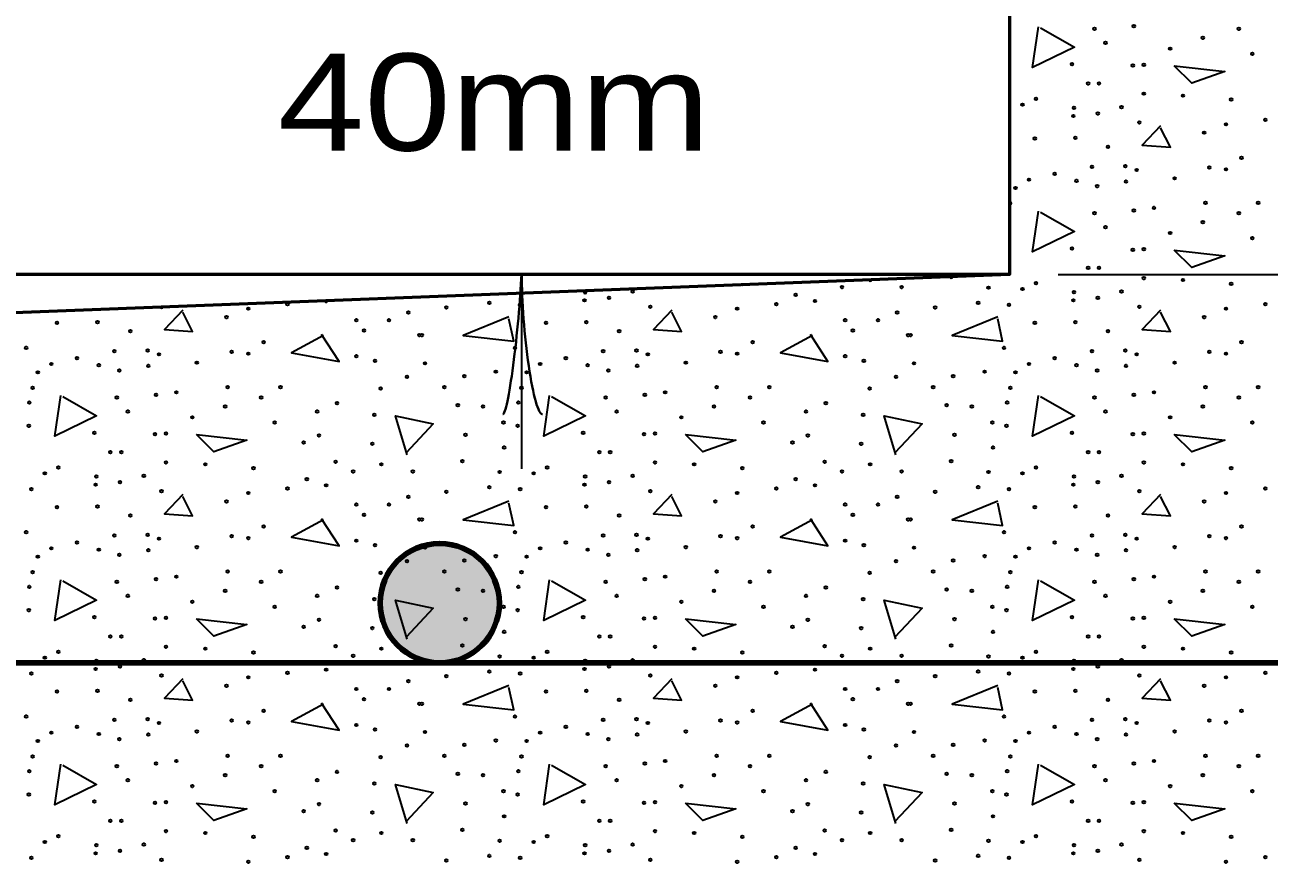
# Model space of a CAD drawing. Extents: x 442 to 1297, y -1132 to -588.
# Drawn here: x 631.58 to 662.37, y -976.12 to -955.39 of the extents above; entities that cross this region are included whole.
import ezdxf
from ezdxf.enums import TextEntityAlignment as Align

# ---------------------------------------------------------------- set-up
doc = ezdxf.new("R2010")
doc.units = 0
doc.header["$LTSCALE"] = 0.96
doc.layers.add('1', color=7, linetype='Continuous', lineweight=35)

msp = doc.modelspace()

# ---------------------------------------------------------------- hatches: boundary and pattern name
at = {"layer": '1'}
msp.add_hatch(color=256, dxfattribs=at).paths.add_polyline_path([(643.3225, -969.6926, 1), (640.3727, -969.6926, 1)])

# ---------------------------------------------------------------- linework, layer by layer
at = {"layer": '1', "lineweight": 53}
msp.add_line((655.9476, -961.5675), (589.3476, -961.5675), dxfattribs=at)
at = {"layer": '1'}
for p, q in [((643.8721, -961.5675), (643.8721, -966.3675)), ((657.1476, -961.5675), (691.5175, -961.5675))]:
    msp.add_line(p, q, dxfattribs=at)
at = {"layer": '1', "lineweight": 106}
msp.add_line((579.7476, -971.1675), (665.8476, -971.1675), dxfattribs=at)
at = {"layer": '1', "lineweight": 53}
msp.add_lwpolyline([(668.5476, -884.2076), (668.5476, -888.4076), (660.1476, -888.4076), (660.1476, -902.8076), (655.9476, -902.8076), (655.9476, -961.5675), (624.6664, -962.7675), (624.6664, -981.1136)], dxfattribs=at)
at = {"layer": '1'}
for points in [[(656.7098, -955.4627), (657.5498, -955.9427), (656.5178, -956.4467), (656.6618, -955.4387)], [(659.6858, -957.8867), (659.2298, -958.3667), (659.9258, -958.4147), (659.6858, -957.9347)], [(656.7098, -960.0227), (657.5498, -960.5027), (656.5178, -961.0067), (656.6618, -959.9987)], [(635.4938, -962.4467), (635.0378, -962.9267), (635.7338, -962.9747), (635.4938, -962.4947)], [(643.5578, -962.6147), (642.4298, -963.0707), (643.6778, -963.2147), (643.5578, -962.6627)], [(647.5898, -962.4467), (647.1338, -962.9267), (647.8298, -962.9747), (647.5898, -962.4947)], [(655.6538, -962.6147), (654.5258, -963.0707), (655.7738, -963.2147), (655.6538, -962.6627)], [(659.6858, -962.4467), (659.2298, -962.9267), (659.9258, -962.9747), (659.6858, -962.4947)], [(638.9738, -963.0707), (638.1818, -963.5027), (639.3578, -963.7187), (638.9258, -963.0467)], [(651.0698, -963.0707), (650.2778, -963.5027), (651.4538, -963.7187), (651.0218, -963.0467)], [(632.5178, -964.5827), (633.3578, -965.0627), (632.3258, -965.5667), (632.4698, -964.5587)], [(644.6138, -964.5827), (645.4538, -965.0627), (644.4218, -965.5667), (644.5658, -964.5587)], [(656.7098, -964.5827), (657.5498, -965.0627), (656.5178, -965.5667), (656.6618, -964.5587)], [(641.0378, -966.0227), (640.7498, -965.0627), (641.6858, -965.2547), (641.0138, -965.9747)], [(653.1338, -966.0227), (652.8458, -965.0627), (653.7818, -965.2547), (653.1098, -965.9747)], [(635.4938, -967.0067), (635.0378, -967.4867), (635.7338, -967.5347), (635.4938, -967.0547)], [(643.5578, -967.1747), (642.4298, -967.6307), (643.6778, -967.7747), (643.5578, -967.2227)], [(647.5898, -967.0067), (647.1338, -967.4867), (647.8298, -967.5347), (647.5898, -967.0547)], [(655.6538, -967.1747), (654.5258, -967.6307), (655.7738, -967.7747), (655.6538, -967.2227)], [(659.6858, -967.0067), (659.2298, -967.4867), (659.9258, -967.5347), (659.6858, -967.0547)], [(638.9738, -967.6307), (638.1818, -968.0627), (639.3578, -968.2787), (638.9258, -967.6067)], [(651.0698, -967.6307), (650.2778, -968.0627), (651.4538, -968.2787), (651.0218, -967.6067)], [(632.5178, -969.1427), (633.3578, -969.6227), (632.3258, -970.1267), (632.4698, -969.1187)], [(644.6138, -969.1427), (645.4538, -969.6227), (644.4218, -970.1267), (644.5658, -969.1187)], [(656.7098, -969.1427), (657.5498, -969.6227), (656.5178, -970.1267), (656.6618, -969.1187)], [(641.0378, -970.5827), (640.7498, -969.6227), (641.6858, -969.8147), (641.0138, -970.5347)], [(653.1338, -970.5827), (652.8458, -969.6227), (653.7818, -969.8147), (653.1098, -970.5347)], [(635.4938, -971.5667), (635.0378, -972.0467), (635.7338, -972.0947), (635.4938, -971.6147)], [(647.5898, -971.5667), (647.1338, -972.0467), (647.8298, -972.0947), (647.5898, -971.6147)], [(659.6858, -971.5667), (659.2298, -972.0467), (659.9258, -972.0947), (659.6858, -971.6147)], [(643.5578, -971.7347), (642.4298, -972.1907), (643.6778, -972.3347), (643.5578, -971.7827)], [(655.6538, -971.7347), (654.5258, -972.1907), (655.7738, -972.3347), (655.6538, -971.7827)], [(638.9738, -972.1907), (638.1818, -972.6227), (639.3578, -972.8387), (638.9258, -972.1667)], [(651.0698, -972.1907), (650.2778, -972.6227), (651.4538, -972.8387), (651.0218, -972.1667)], [(632.5178, -973.7027), (633.3578, -974.1827), (632.3258, -974.6867), (632.4698, -973.6787)], [(644.6138, -973.7027), (645.4538, -974.1827), (644.4218, -974.6867), (644.5658, -973.6787)], [(656.7098, -973.7027), (657.5498, -974.1827), (656.5178, -974.6867), (656.6618, -973.6787)], [(641.0378, -975.1427), (640.7498, -974.1827), (641.6858, -974.3747), (641.0138, -975.0947)], [(653.1338, -975.1427), (652.8458, -974.1827), (653.7818, -974.3747), (653.1098, -975.0947)]]:
    msp.add_lwpolyline(points, dxfattribs=at)
for points in [[(660.0218, -956.3987), (661.2698, -956.5427), (660.4538, -956.8307)], [(660.0218, -960.9587), (661.2698, -961.1027), (660.4538, -961.3907)], [(635.8298, -965.5187), (637.0778, -965.6627), (636.2618, -965.9507)], [(647.9258, -965.5187), (649.1738, -965.6627), (648.3578, -965.9507)], [(660.0218, -965.5187), (661.2698, -965.6627), (660.4538, -965.9507)], [(635.8298, -970.0787), (637.0778, -970.2227), (636.2618, -970.5107)], [(647.9258, -970.0787), (649.1738, -970.2227), (648.3578, -970.5107)], [(660.0218, -970.0787), (661.2698, -970.2227), (660.4538, -970.5107)], [(635.8298, -974.6387), (637.0778, -974.7827), (636.2618, -975.0707)], [(647.9258, -974.6387), (649.1738, -974.7827), (648.3578, -975.0707)], [(660.0218, -974.6387), (661.2698, -974.7827), (660.4538, -975.0707)]]:
    msp.add_lwpolyline(points, close=True, dxfattribs=at)
for centre in [(658.0499, -955.4852), (659.0201, -955.4216), (661.6216, -955.4852), (658.3204, -955.8353), (660.731, -955.708), (659.9199, -955.9785), (661.9555, -956.1058), (657.4933, -956.3603), (658.9965, -956.3948), (659.2678, -956.3761), (657.891, -956.8376), (658.1613, -956.8376), (659.2678, -957.0921), (660.238, -957.1398), (656.2688, -957.3625), (656.6028, -957.2194), (657.5411, -957.4421), (658.7179, -957.4261), (661.4308, -957.2352), (657.5252, -957.6431), (658.1295, -957.5795), (662.2737, -957.7385), (659.1565, -957.8021), (660.7628, -958.0567), (661.3036, -957.8499), (656.5709, -958.1999), (657.5729, -958.184), (658.384, -958.4066), (661.6852, -958.6771), (657.9863, -958.8998), (658.8134, -958.8839), (659.0929, -958.9794), (660.89, -958.9158), (661.3036, -958.9635), (656.4278, -959.2181), (657.0639, -959.0748), (657.6047, -959.2498), (658.8292, -959.2657), (660.0312, -959.1862), (656.0938, -959.4248), (658.1137, -959.3771), (659.5222, -959.918), (660.7945, -959.7907), (662.0987, -959.7907), (658.0499, -960.0452), (659.0201, -959.9816), (661.6216, -960.0452), (658.3204, -960.3953), (659.9199, -960.5385), (660.731, -960.268), (661.9555, -960.6658), (657.4933, -960.9203), (658.9965, -960.9548), (659.2678, -960.9361), (657.891, -961.3976), (658.1613, -961.3976), (656.6028, -961.7794), (659.2678, -961.6521), (660.238, -961.6998), (661.4308, -961.7952), (646.6219, -961.9861), (650.6548, -962.0657), (651.7998, -961.8749), (653.2789, -961.8749), (655.4259, -961.8907), (656.2688, -961.9225), (657.5411, -962.0021), (658.7179, -961.9861), (637.1116, -962.4099), (638.0817, -962.2985), (642.0098, -962.3781), (643.0754, -962.2667), (643.8388, -962.3145), (645.4292, -962.2031), (646.0335, -962.1395), (647.0605, -962.3621), (649.2076, -962.4099), (650.1777, -962.2985), (651.1318, -962.219), (654.1058, -962.3781), (655.1714, -962.2667), (655.9348, -962.3145), (657.5252, -962.2031), (658.1295, -962.1395), (659.1565, -962.3621), (661.3036, -962.4099), (662.2737, -962.2985), (636.5708, -962.6167), (639.7833, -962.6962), (640.5944, -962.6962), (641.0716, -962.5053), (648.6668, -962.6167), (651.8793, -962.6962), (652.6904, -962.6962), (653.1676, -962.5053), (660.7628, -962.6167), (632.3789, -962.7599), (633.3809, -962.744), (634.192, -962.9666), (639.9742, -962.9508), (644.4749, -962.7599), (645.4769, -962.744), (646.288, -962.9666), (652.0702, -962.9508), (656.5709, -962.7599), (657.5729, -962.744), (658.384, -962.9666), (637.4932, -963.2371), (641.3419, -963.0621), (641.4055, -963.0621), (649.5892, -963.2371), (653.4379, -963.0621), (653.5015, -963.0621), (661.6852, -963.2371), (631.6155, -963.3803), (632.8719, -963.6348), (633.7943, -963.4598), (634.6214, -963.4439), (634.9009, -963.5394), (636.698, -963.4758), (637.1116, -963.5235), (639.7834, -963.5872), (643.7115, -963.3803), (644.9679, -963.6348), (645.8903, -963.4598), (646.7174, -963.4439), (646.9969, -963.5394), (648.794, -963.4758), (649.2076, -963.5235), (651.8794, -963.5872), (655.8075, -963.3803), (657.0639, -963.6348), (657.9863, -963.4598), (658.8134, -963.4439), (659.0929, -963.5394), (660.89, -963.4758), (661.3036, -963.5235), (632.2358, -963.7781), (633.4127, -963.8098), (633.9217, -963.9371), (634.6372, -963.8257), (635.8392, -963.7462), (640.2445, -963.6984), (641.4851, -963.7621), (644.3318, -963.7781), (645.5087, -963.8098), (646.0177, -963.9371), (646.7332, -963.8257), (647.9352, -963.7462), (652.3405, -963.6984), (653.5811, -963.7621), (656.4278, -963.7781), (657.6047, -963.8098), (658.1137, -963.9371), (658.8292, -963.8257), (660.0312, -963.7462), (631.9018, -963.9848), (641.0397, -964.0962), (642.4552, -964.0803), (643.2345, -963.9689), (643.9978, -963.9848), (653.1357, -964.0962), (654.5512, -964.0803), (655.3305, -963.9689), (656.0938, -963.9848), (631.7746, -964.3666), (634.8281, -964.5416), (635.3302, -964.478), (636.6025, -964.3507), (637.9067, -964.3507), (640.3877, -964.3826), (641.9622, -964.3507), (643.8706, -964.3666), (646.9241, -964.5416), (647.4262, -964.478), (648.6985, -964.3507), (650.0027, -964.3507), (652.4837, -964.3826), (654.0582, -964.3507), (655.9666, -964.3666), (659.0201, -964.5416), (659.5222, -964.478), (660.7945, -964.3507), (662.0987, -964.3507), (631.6951, -964.7325), (633.8579, -964.6052), (636.539, -964.828), (637.4296, -964.6052), (639.3062, -964.7485), (642.2961, -964.7962), (642.9163, -964.828), (643.7911, -964.7325), (645.9539, -964.6052), (648.635, -964.828), (649.5256, -964.6052), (651.4022, -964.7485), (654.3921, -964.7962), (655.0123, -964.828), (655.8871, -964.7325), (658.0499, -964.6052), (660.731, -964.828), (661.6216, -964.6052), (634.1284, -964.9553), (635.7279, -965.0985), (638.8132, -964.9553), (640.2286, -965.0348), (646.2244, -964.9553), (647.8239, -965.0985), (650.9092, -964.9553), (652.3246, -965.0348), (658.3204, -964.9553), (659.9199, -965.0985), (631.6792, -965.3053), (633.3013, -965.4803), (637.7635, -965.2258), (643.4253, -965.2258), (643.7752, -965.3053), (645.3973, -965.4803), (649.8595, -965.2258), (655.5213, -965.2258), (655.8712, -965.3053), (657.4933, -965.4803), (661.9555, -965.2258), (634.8045, -965.5148), (635.0758, -965.4961), (638.4792, -965.7189), (638.861, -965.5439), (640.1809, -965.7507), (642.4869, -965.528), (646.9005, -965.5148), (647.1718, -965.4961), (650.5752, -965.7189), (650.957, -965.5439), (652.2769, -965.7507), (654.5829, -965.528), (658.9965, -965.5148), (659.2678, -965.4961), (633.699, -965.9576), (633.9693, -965.9576), (643.4412, -965.8462), (645.795, -965.9576), (646.0653, -965.9576), (655.5372, -965.8462), (657.891, -965.9576), (658.1613, -965.9576), (632.4108, -966.3394), (635.0758, -966.2121), (636.046, -966.2598), (637.2388, -966.3552), (639.2744, -966.1962), (640.4036, -966.2598), (642.4075, -966.1802), (644.5068, -966.3394), (647.1718, -966.2121), (648.142, -966.2598), (649.3348, -966.3552), (651.3704, -966.1962), (652.4996, -966.2598), (654.5035, -966.1802), (656.6028, -966.3394), (659.2678, -966.2121), (660.238, -966.2598), (661.4308, -966.3552), (632.0768, -966.4825), (633.3491, -966.5621), (633.9375, -966.6995), (634.5259, -966.5461), (638.5588, -966.6257), (639.7038, -966.4349), (641.1829, -966.4349), (643.3299, -966.4507), (644.1728, -966.4825), (645.4451, -966.5621), (646.0335, -966.6995), (646.6219, -966.5461), (650.6548, -966.6257), (651.7998, -966.4349), (653.2789, -966.4349), (655.4259, -966.4507), (656.2688, -966.4825), (657.5411, -966.5621), (658.1295, -966.6995), (658.7179, -966.5461), (631.7428, -966.8745), (633.3332, -966.7631), (634.9645, -966.9221), (637.1116, -966.9699), (638.0817, -966.8585), (639.0358, -966.779), (642.0098, -966.9381), (643.0754, -966.8267), (643.8388, -966.8745), (645.4292, -966.7631), (647.0605, -966.9221), (649.2076, -966.9699), (650.1777, -966.8585), (651.1318, -966.779), (654.1058, -966.9381), (655.1714, -966.8267), (655.9348, -966.8745), (657.5252, -966.7631), (659.1565, -966.9221), (661.3036, -966.9699), (662.2737, -966.8585), (632.3789, -967.3199), (633.3809, -967.304), (636.5708, -967.1767), (639.7833, -967.2562), (640.5944, -967.2562), (641.0716, -967.0653), (644.4749, -967.3199), (645.4769, -967.304), (648.6668, -967.1767), (651.8793, -967.2562), (652.6904, -967.2562), (653.1676, -967.0653), (656.5709, -967.3199), (657.5729, -967.304), (660.7628, -967.1767), (634.192, -967.5266), (639.9742, -967.5108), (641.3419, -967.6221), (641.4055, -967.6221), (646.288, -967.5266), (652.0702, -967.5108), (653.4379, -967.6221), (653.5015, -967.6221), (658.384, -967.5266), (631.6155, -967.9403), (637.4932, -967.7971), (643.7115, -967.9403), (649.5892, -967.7971), (655.8075, -967.9403), (661.6852, -967.7971), (632.8719, -968.1948), (633.7943, -968.0198), (634.6214, -968.0039), (634.9009, -968.0994), (636.698, -968.0358), (637.1116, -968.0835), (639.7834, -968.1472), (640.2445, -968.2584), (644.9679, -968.1948), (645.8903, -968.0198), (646.7174, -968.0039), (646.9969, -968.0994), (648.794, -968.0358), (649.2076, -968.0835), (651.8794, -968.1472), (652.3405, -968.2584), (657.0639, -968.1948), (657.9863, -968.0198), (658.8134, -968.0039), (659.0929, -968.0994), (660.89, -968.0358), (661.3036, -968.0835), (631.9018, -968.5448), (632.2358, -968.3381), (633.4127, -968.3698), (633.9217, -968.4971), (634.6372, -968.3857), (635.8392, -968.3062), (641.4851, -968.3221), (643.2345, -968.5289), (643.9978, -968.5448), (644.3318, -968.3381), (645.5087, -968.3698), (646.0177, -968.4971), (646.7332, -968.3857), (647.9352, -968.3062), (653.5811, -968.3221), (655.3305, -968.5289), (656.0938, -968.5448), (656.4278, -968.3381), (657.6047, -968.3698), (658.1137, -968.4971), (658.8292, -968.3857), (660.0312, -968.3062), (641.0397, -968.6562), (642.4552, -968.6403), (653.1357, -968.6562), (654.5512, -968.6403), (631.7746, -968.9266), (633.8579, -969.1652), (634.8281, -969.1016), (635.3302, -969.038), (636.6025, -968.9107), (637.4296, -969.1652), (637.9067, -968.9107), (640.3877, -968.9426), (641.9622, -968.9107), (643.8706, -968.9266), (645.9539, -969.1652), (646.9241, -969.1016), (647.4262, -969.038), (648.6985, -968.9107), (649.5256, -969.1652), (650.0027, -968.9107), (652.4837, -968.9426), (654.0582, -968.9107), (655.9666, -968.9266), (658.0499, -969.1652), (659.0201, -969.1016), (659.5222, -969.038), (660.7945, -968.9107), (661.6216, -969.1652), (662.0987, -968.9107), (631.6951, -969.2925), (636.539, -969.388), (639.3062, -969.3085), (642.2961, -969.3562), (642.9163, -969.388), (643.7911, -969.2925), (648.635, -969.388), (651.4022, -969.3085), (654.3921, -969.3562), (655.0123, -969.388), (655.8871, -969.2925), (660.731, -969.388), (634.1284, -969.5153), (635.7279, -969.6585), (637.7635, -969.7858), (638.8132, -969.5153), (640.2286, -969.5948), (643.4253, -969.7858), (646.2244, -969.5153), (647.8239, -969.6585), (649.8595, -969.7858), (650.9092, -969.5153), (652.3246, -969.5948), (655.5213, -969.7858), (658.3204, -969.5153), (659.9199, -969.6585), (661.9555, -969.7858), (631.6792, -969.8653), (633.3013, -970.0403), (634.8045, -970.0748), (635.0758, -970.0561), (638.861, -970.1039), (642.4869, -970.088), (643.7752, -969.8653), (645.3973, -970.0403), (646.9005, -970.0748), (647.1718, -970.0561), (650.957, -970.1039), (654.5829, -970.088), (655.8712, -969.8653), (657.4933, -970.0403), (658.9965, -970.0748), (659.2678, -970.0561), (638.4792, -970.2789), (640.1809, -970.3107), (643.4412, -970.4062), (650.5752, -970.2789), (652.2769, -970.3107), (655.5372, -970.4062), (633.699, -970.5176), (633.9693, -970.5176), (645.795, -970.5176), (646.0653, -970.5176), (657.891, -970.5176), (658.1613, -970.5176), (632.4108, -970.8994), (635.0758, -970.7721), (636.046, -970.8198), (637.2388, -970.9152), (639.2744, -970.7562), (639.7038, -970.9949), (640.4036, -970.8198), (641.1829, -970.9949), (642.4075, -970.7402), (643.3299, -971.0107), (644.5068, -970.8994), (647.1718, -970.7721), (648.142, -970.8198), (649.3348, -970.9152), (651.3704, -970.7562), (651.7998, -970.9949), (652.4996, -970.8198), (653.2789, -970.9949), (654.5035, -970.7402), (655.4259, -971.0107), (656.6028, -970.8994), (659.2678, -970.7721), (660.238, -970.8198), (661.4308, -970.9152), (632.0768, -971.0425), (633.3332, -971.3231), (633.3491, -971.1221), (633.9375, -971.2595), (634.5259, -971.1061), (638.5588, -971.1857), (639.0358, -971.339), (644.1728, -971.0425), (645.4292, -971.3231), (645.4451, -971.1221), (646.0335, -971.2595), (646.6219, -971.1061), (650.6548, -971.1857), (651.1318, -971.339), (656.2688, -971.0425), (657.5252, -971.3231), (657.5411, -971.1221), (658.1295, -971.2595), (658.7179, -971.1061), (631.7428, -971.4345), (634.9645, -971.4821), (637.1116, -971.5299), (638.0817, -971.4185), (641.0716, -971.6253), (642.0098, -971.4981), (643.0754, -971.3867), (643.8388, -971.4345), (647.0605, -971.4821), (649.2076, -971.5299), (650.1777, -971.4185), (653.1676, -971.6253), (654.1058, -971.4981), (655.1714, -971.3867), (655.9348, -971.4345), (659.1565, -971.4821), (661.3036, -971.5299), (662.2737, -971.4185), (632.3789, -971.8799), (633.3809, -971.864), (636.5708, -971.7367), (639.7833, -971.8162), (640.5944, -971.8162), (644.4749, -971.8799), (645.4769, -971.864), (648.6668, -971.7367), (651.8793, -971.8162), (652.6904, -971.8162), (656.5709, -971.8799), (657.5729, -971.864), (660.7628, -971.7367), (634.192, -972.0866), (639.9742, -972.0708), (641.3419, -972.1821), (641.4055, -972.1821), (646.288, -972.0866), (652.0702, -972.0708), (653.4379, -972.1821), (653.5015, -972.1821), (658.384, -972.0866), (631.6155, -972.5003), (634.6214, -972.5639), (637.4932, -972.3571), (643.7115, -972.5003), (646.7174, -972.5639), (649.5892, -972.3571), (655.8075, -972.5003), (658.8134, -972.5639), (661.6852, -972.3571), (632.8719, -972.7548), (633.7943, -972.5798), (634.9009, -972.6594), (635.8392, -972.8662), (636.698, -972.5958), (637.1116, -972.6435), (639.7834, -972.7072), (640.2445, -972.8184), (641.4851, -972.8821), (644.9679, -972.7548), (645.8903, -972.5798), (646.9969, -972.6594), (647.9352, -972.8662), (648.794, -972.5958), (649.2076, -972.6435), (651.8794, -972.7072), (652.3405, -972.8184), (653.5811, -972.8821), (657.0639, -972.7548), (657.9863, -972.5798), (659.0929, -972.6594), (660.0312, -972.8662), (660.89, -972.5958), (661.3036, -972.6435), (631.9018, -973.1048), (632.2358, -972.8981), (633.4127, -972.9298), (633.9217, -973.0571), (634.6372, -972.9457), (643.2345, -973.0889), (643.9978, -973.1048), (644.3318, -972.8981), (645.5087, -972.9298), (646.0177, -973.0571), (646.7332, -972.9457), (655.3305, -973.0889), (656.0938, -973.1048), (656.4278, -972.8981), (657.6047, -972.9298), (658.1137, -973.0571), (658.8292, -972.9457), (631.7746, -973.4866), (636.6025, -973.4707), (637.9067, -973.4707), (641.0397, -973.2162), (641.9622, -973.4707), (642.4552, -973.2003), (643.8706, -973.4866), (648.6985, -973.4707), (650.0027, -973.4707), (653.1357, -973.2162), (654.0582, -973.4707), (654.5512, -973.2003), (655.9666, -973.4866), (660.7945, -973.4707), (662.0987, -973.4707), (633.8579, -973.7252), (634.8281, -973.6616), (635.3302, -973.598), (637.4296, -973.7252), (640.3877, -973.5026), (645.9539, -973.7252), (646.9241, -973.6616), (647.4262, -973.598), (649.5256, -973.7252), (652.4837, -973.5026), (658.0499, -973.7252), (659.0201, -973.6616), (659.5222, -973.598), (661.6216, -973.7252), (631.6951, -973.8525), (634.1284, -974.0753), (636.539, -973.948), (638.8132, -974.0753), (639.3062, -973.8685), (642.2961, -973.9162), (642.9163, -973.948), (643.7911, -973.8525), (646.2244, -974.0753), (648.635, -973.948), (650.9092, -974.0753), (651.4022, -973.8685), (654.3921, -973.9162), (655.0123, -973.948), (655.8871, -973.8525), (658.3204, -974.0753), (660.731, -973.948), (635.7279, -974.2185), (637.7635, -974.3458), (640.2286, -974.1548), (643.4253, -974.3458), (647.8239, -974.2185), (649.8595, -974.3458), (652.3246, -974.1548), (655.5213, -974.3458), (659.9199, -974.2185), (661.9555, -974.3458), (631.6792, -974.4253), (633.3013, -974.6003), (634.8045, -974.6348), (635.0758, -974.6161), (638.861, -974.6639), (642.4869, -974.648), (643.7752, -974.4253), (645.3973, -974.6003), (646.9005, -974.6348), (647.1718, -974.6161), (650.957, -974.6639), (654.5829, -974.648), (655.8712, -974.4253), (657.4933, -974.6003), (658.9965, -974.6348), (659.2678, -974.6161), (638.4792, -974.8389), (640.1809, -974.8707), (643.4412, -974.9662), (650.5752, -974.8389), (652.2769, -974.8707), (655.5372, -974.9662), (633.699, -975.0776), (633.9693, -975.0776), (635.0758, -975.3321), (639.2744, -975.3162), (642.4075, -975.3002), (645.795, -975.0776), (646.0653, -975.0776), (647.1718, -975.3321), (651.3704, -975.3162), (654.5035, -975.3002), (657.891, -975.0776), (658.1613, -975.0776), (659.2678, -975.3321), (632.0768, -975.6025), (632.4108, -975.4594), (636.046, -975.3798), (637.2388, -975.4752), (639.7038, -975.5549), (640.4036, -975.3798), (641.1829, -975.5549), (643.3299, -975.5707), (644.1728, -975.6025), (644.5068, -975.4594), (648.142, -975.3798), (649.3348, -975.4752), (651.7998, -975.5549), (652.4996, -975.3798), (653.2789, -975.5549), (655.4259, -975.5707), (656.2688, -975.6025), (656.6028, -975.4594), (660.238, -975.3798), (661.4308, -975.4752), (633.3332, -975.8831), (633.3491, -975.6821), (633.9375, -975.8195), (634.5259, -975.6661), (638.5588, -975.7457), (639.0358, -975.899), (643.0754, -975.9467), (645.4292, -975.8831), (645.4451, -975.6821), (646.0335, -975.8195), (646.6219, -975.6661), (650.6548, -975.7457), (651.1318, -975.899), (655.1714, -975.9467), (657.5252, -975.8831), (657.5411, -975.6821), (658.1295, -975.8195), (658.7179, -975.6661), (631.7428, -975.9945), (634.9645, -976.0421), (637.1116, -976.0899), (638.0817, -975.9785), (642.0098, -976.0581), (643.8388, -975.9945), (647.0605, -976.0421), (649.2076, -976.0899), (650.1777, -975.9785), (654.1058, -976.0581), (655.9348, -975.9945), (659.1565, -976.0421), (661.3036, -976.0899), (662.2737, -975.9785)]:
    msp.add_circle(centre, 0.0318, dxfattribs=at)
at = {"layer": '1', "lineweight": 106}
msp.add_circle((641.8476, -969.6926), 1.4749, dxfattribs=at)
at = {"layer": '1'}
for centre, start, end in [((655.9348, -957.7545), 293.85588, 66.14412), ((655.9666, -959.8066), 233.2205, 126.7795), ((652.4996, -961.6998), 182.20415, 2.18962), ((654.5035, -961.6202), 187.00262, 357.39115), ((645.4451, -962.0021), 96.79646, 87.59731), ((649.3348, -961.7952), 236.96293, 307.43084), ((634.9645, -962.3621), 201.13504, 343.25873), ((639.0358, -962.219), 177.26126, 7.13251)]:
    msp.add_arc(centre, 0.0318, start, end, dxfattribs=at)
at = {"layer": '1', "lineweight": 40}
for centre, major_axis, ratio, start_param, end_param in [((643.6182, -962.9121), (0.2108, 2.1077), 0.07063, 3.1407148, 5.41811), ((644.2037, -962.8769), (-0.1874, 2.1428), 0.122415, 0.8963533, 3.1415927)]:
    msp.add_ellipse(centre, major_axis=major_axis, ratio=ratio, start_param=start_param, end_param=end_param, dxfattribs=at)

# ---------------------------------------------------------------- texts
at = {"layer": '1', "width": 1.2}
msp.add_text('40mm', height=2.4, dxfattribs=at).set_placement((643.19, -958.4999), align=Align.CENTER)

doc.saveas('drawing.dxf')
